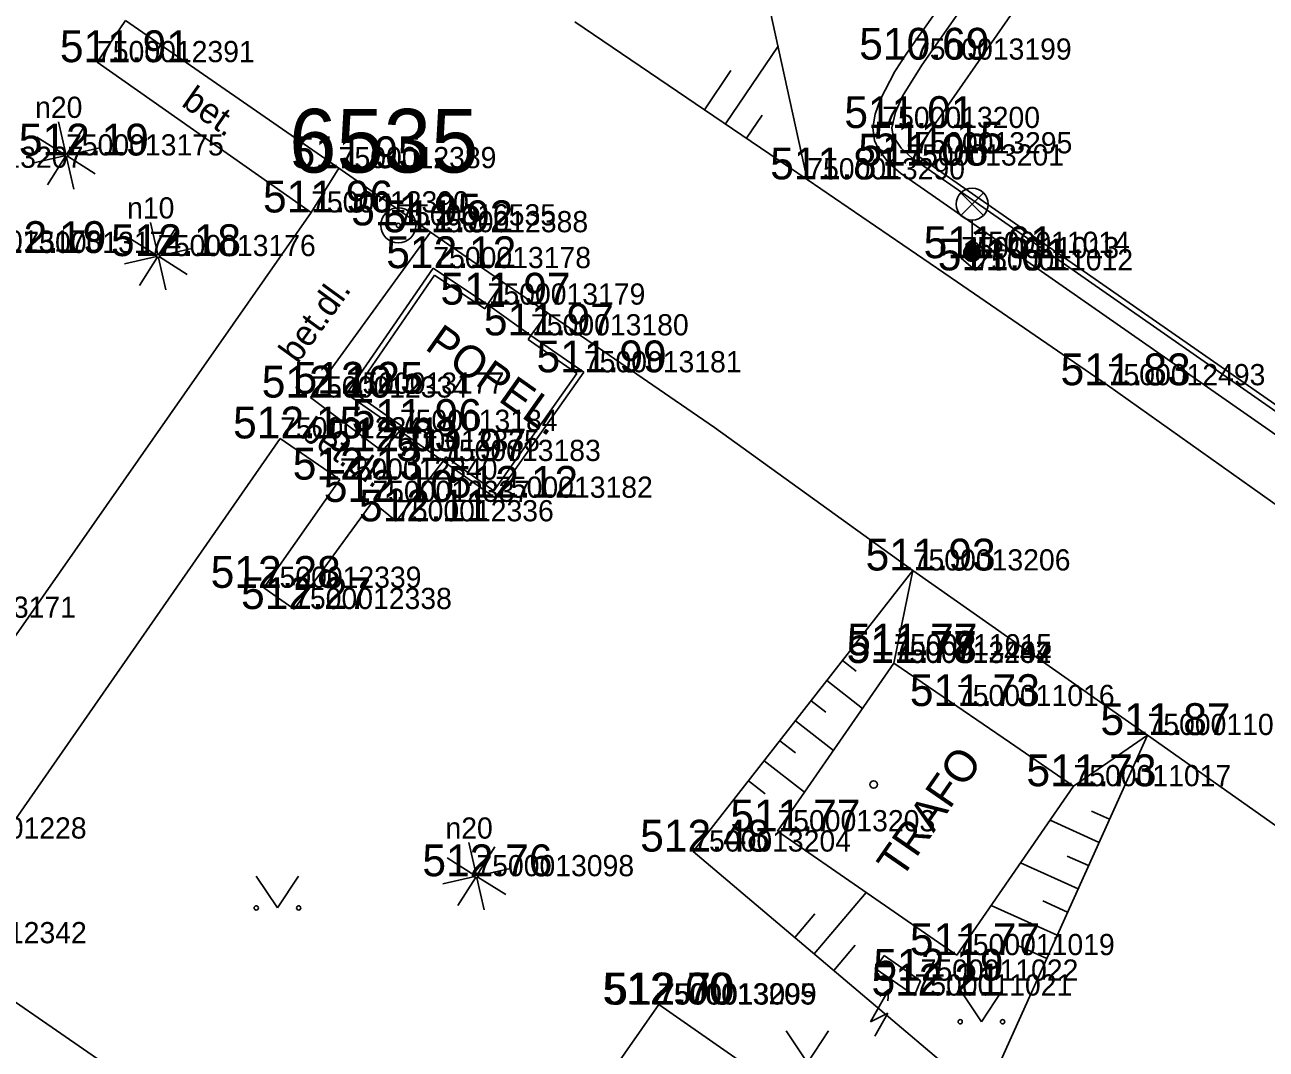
# Model space of a CAD drawing. Extents: x -669251 to -668549, y -1128351 to -1127698.
# Drawn here: x -668939.39 to -668910.12, y -1127892.22 to -1127868.08 of the extents above; entities that cross this region are included whole.
import ezdxf

# ---------------------------------------------------------------- set-up
doc = ezdxf.new("R2010")
doc.units = 0
for name, color, linetype in [('Vrstva 1', 7, 'Continuous'), ('Vrstva 10', 7, 'Continuous'), ('Vrstva 11', 7, 'Continuous'), ('Vrstva 14', 7, 'Continuous'), ('Vrstva 15', 7, 'Continuous'), ('Vrstva 2', 7, 'Continuous'), ('Vrstva 22', 7, 'Continuous'), ('Vrstva 24', 7, 'Continuous'), ('Vrstva 3', 7, 'Continuous'), ('Vrstva 33', 7, 'Continuous'), ('Vrstva 36', 7, 'Continuous'), ('Vrstva 40', 7, 'Continuous'), ('Vrstva 42', 7, 'Continuous'), ('Vrstva 47', 7, 'Continuous'), ('Vrstva 5', 7, 'Continuous'), ('Vrstva 58', 7, 'Continuous'), ('Vrstva 6', 7, 'Continuous'), ('Vrstva 63', 7, 'Continuous'), ('Vrstva 7', 7, 'Continuous')]:
    doc.layers.add(name, color=color, linetype=linetype)

msp = doc.modelspace()

# ---------------------------------------------------------------- linework, layer by layer
at = {"layer": 'Vrstva 1'}
for p, q in [((-668937.686, -1127868.956), (-668937.686, -1127868.956)), ((-668918.425, -1127868.897), (-668918.425, -1127868.897)), ((-668919.171, -1127870.508), (-668919.171, -1127870.508)), ((-668938.416, -1127871.156), (-668938.416, -1127871.156)), ((-668918.409, -1127871.106), (-668918.409, -1127871.106)), ((-668931.988, -1127871.455), (-668931.988, -1127871.455)), ((-668918.605, -1127871.394), (-668918.605, -1127871.394)), ((-668920.94, -1127871.719), (-668920.94, -1127871.719)), ((-668932.638, -1127872.499), (-668932.638, -1127872.499)), ((-668930.582, -1127872.804), (-668930.582, -1127872.804)), ((-668930.582, -1127872.804), (-668930.582, -1127872.804)), ((-668929.825, -1127872.966), (-668929.825, -1127872.966)), ((-668936.247, -1127873.528), (-668936.247, -1127873.528)), ((-668917.308, -1127873.577), (-668917.308, -1127873.577)), ((-668917.052, -1127873.453), (-668917.052, -1127873.453)), ((-668929.757, -1127873.812), (-668929.757, -1127873.812)), ((-668916.976, -1127873.865), (-668916.976, -1127873.865)), ((-668928.476, -1127874.672), (-668928.476, -1127874.672)), ((-668927.454, -1127875.397), (-668927.454, -1127875.397)), ((-668926.207, -1127876.268), (-668926.207, -1127876.268)), ((-668913.858, -1127876.573), (-668913.858, -1127876.573)), ((-668932.656, -1127876.863), (-668932.656, -1127876.863)), ((-668931.801, -1127876.772), (-668931.801, -1127876.772)), ((-668930.546, -1127877.65), (-668930.546, -1127877.65)), ((-668933.368, -1127877.826), (-668933.368, -1127877.826)), ((-668930.965, -1127878.128), (-668930.965, -1127878.128)), ((-668929.527, -1127878.359), (-668929.527, -1127878.359)), ((-668931.961, -1127878.798), (-668931.961, -1127878.798)), ((-668928.3, -1127879.226), (-668928.3, -1127879.226)), ((-668931.193, -1127879.323), (-668931.193, -1127879.323)), ((-668930.635, -1127879.781), (-668930.635, -1127879.781)), ((-668918.453, -1127880.94), (-668918.453, -1127880.94)), ((-668933.754, -1127881.349), (-668933.754, -1127881.349)), ((-668933.038, -1127881.849), (-668933.038, -1127881.849)), ((-668918.888, -1127882.941), (-668918.888, -1127882.941)), ((-668918.903, -1127883.115), (-668918.903, -1127883.115)), ((-668918.903, -1127883.116), (-668918.903, -1127883.116)), ((-668918.9, -1127883.121), (-668918.9, -1127883.121)), ((-668917.412, -1127884.136), (-668917.412, -1127884.136)), ((-668912.918, -1127884.819), (-668912.918, -1127884.819)), ((-668914.663, -1127886.026), (-668914.663, -1127886.026)), ((-668921.643, -1127887.089), (-668921.643, -1127887.089)), ((-668923.628, -1127887.567), (-668923.628, -1127887.567)), ((-668928.741, -1127888.148), (-668928.741, -1127888.148)), ((-668917.41, -1127890.008), (-668917.41, -1127890.008)), ((-668918.267, -1127890.61), (-668918.267, -1127890.61)), ((-668924.459, -1127891.17), (-668924.459, -1127891.17)), ((-668924.438, -1127891.175), (-668924.438, -1127891.175)), ((-668918.411, -1127890.962), (-668918.411, -1127890.962))]:
    msp.add_line(p, q, dxfattribs=at)
at = {"layer": 'Vrstva 10'}
for p, q in [((-668918.18, -1127868.156), (-668915.19, -1127863.895)), ((-668937.686, -1127868.956), (-668937.017, -1127867.976)), ((-668937.017, -1127867.976), (-668931.988, -1127871.455)), ((-668920.94, -1127871.719), (-668926.424, -1127868.005)), ((-668932.638, -1127872.499), (-668937.686, -1127868.956)), ((-668931.988, -1127871.455), (-668929.825, -1127872.966)), ((-668917.557, -1127871.85), (-668909.122, -1127877.73)), ((-668917.814, -1127872.219), (-668909.391, -1127878.091)), ((-668932.638, -1127872.499), (-668953.974, -1127903.041)), ((-668929.825, -1127872.966), (-668932.656, -1127876.863)), ((-668916.98, -1127873.199), (-668917.308, -1127873.577)), ((-668916.648, -1127873.487), (-668916.98, -1127873.199)), ((-668917.308, -1127873.577), (-668916.976, -1127873.865)), ((-668916.648, -1127873.487), (-668916.976, -1127873.865)), ((-668928.476, -1127874.672), (-668928.114, -1127874.142)), ((-668927.454, -1127875.397), (-668927.064, -1127874.864)), ((-668932.656, -1127876.863), (-668930.965, -1127878.128)), ((-668930.965, -1127878.128), (-668930.546, -1127877.65)), ((-668933.368, -1127877.826), (-668941.646, -1127889.728)), ((-668933.368, -1127877.826), (-668931.961, -1127878.798)), ((-668930.635, -1127879.781), (-668929.527, -1127878.359)), ((-668931.961, -1127878.798), (-668933.754, -1127881.349)), ((-668933.038, -1127881.849), (-668931.193, -1127879.323)), ((-668931.193, -1127879.323), (-668930.635, -1127879.781)), ((-668918.453, -1127880.94), (-668912.918, -1127884.819)), ((-668933.754, -1127881.349), (-668933.038, -1127881.849)), ((-668941.646, -1127889.728), (-668930.773, -1127897.183))]:
    msp.add_line(p, q, dxfattribs=at)
for points in [[(-668917.392, -1127867.816), (-668917.816, -1127868.421), (-668918.241, -1127869.026), (-668918.695, -1127869.754), (-668918.862, -1127870.135), (-668918.946, -1127870.508), (-668918.914, -1127870.701), (-668918.729, -1127870.985), (-668918.471, -1127871.214), (-668918.014, -1127871.532), (-668917.557, -1127871.85)], [(-668918.18, -1127868.156), (-668918.395, -1127868.462), (-668918.609, -1127868.768), (-668918.879, -1127869.179), (-668919.221, -1127869.844), (-668919.336, -1127870.18), (-668919.396, -1127870.508), (-668919.356, -1127870.799), (-668919.254, -1127871.02), (-668919.021, -1127871.329), (-668918.739, -1127871.574), (-668918.277, -1127871.897), (-668917.814, -1127872.219)], [(-668920.94, -1127871.719), (-668917.399, -1127874.146), (-668913.858, -1127876.573), (-668908.746, -1127880.198), (-668903.643, -1127883.845), (-668902.475, -1127884.553), (-668901.24, -1127885.179), (-668900.643, -1127885.444), (-668899.726, -1127885.752), (-668898.8, -1127885.974), (-668897.949, -1127886.123), (-668897.173, -1127886.216), (-668896.481, -1127886.261), (-668895.264, -1127886.241), (-668894.37, -1127886.127), (-668893.723, -1127885.975), (-668893.256, -1127885.821), (-668892.593, -1127885.518), (-668891.985, -1127885.123), (-668889.349, -1127883.09), (-668886.713, -1127881.057)], [(-668929.825, -1127872.966), (-668928.114, -1127874.142), (-668927.064, -1127874.864), (-668923.128, -1127877.569), (-668918.453, -1127880.94)], [(-668903.409, -1127892.816), (-668904.098, -1127891.771), (-668904.901, -1127890.785), (-668905.468, -1127890.18), (-668906.088, -1127889.65), (-668909.503, -1127887.234), (-668912.918, -1127884.819)]]:
    msp.add_lwpolyline(points, dxfattribs=at)
at = {"layer": 'Vrstva 11'}
for p, q in [((-668931.988, -1127871.455), (-668932.638, -1127872.499)), ((-668928.476, -1127874.672), (-668927.454, -1127875.397)), ((-668930.546, -1127877.65), (-668929.527, -1127878.359))]:
    msp.add_line(p, q, dxfattribs=at)
at = {"layer": 'Vrstva 14'}
for p, q in [((-668921.884, -1127867.416), (-668920.94, -1127871.719)), ((-668923.628, -1127887.567), (-668918.453, -1127880.94)), ((-668918.453, -1127880.94), (-668918.9, -1127883.121)), ((-668912.918, -1127884.819), (-668916.774, -1127893.365)), ((-668914.663, -1127886.026), (-668912.918, -1127884.819)), ((-668916.774, -1127893.365), (-668923.628, -1127887.567))]:
    msp.add_line(p, q, dxfattribs=at)
at = {"layer": 'Vrstva 15'}
for p, q in [((-668922.869, -1127870.413), (-668921.628, -1127868.581)), ((-668923.366, -1127870.076), (-668922.742, -1127869.155)), ((-668922.372, -1127870.749), (-668922.004, -1127870.205)), ((-668920.111, -1127883.063), (-668919.786, -1127883.317)), ((-668920.48, -1127883.535), (-668919.64, -1127884.191)), ((-668920.849, -1127884.009), (-668920.502, -1127884.28)), ((-668921.218, -1127884.481), (-668920.323, -1127885.18)), ((-668921.588, -1127884.954), (-668921.219, -1127885.242)), ((-668921.957, -1127885.427), (-668921.007, -1127886.169)), ((-668922.326, -1127885.9), (-668921.935, -1127886.205)), ((-668914.06, -1127887.351), (-668915.217, -1127886.829)), ((-668913.814, -1127886.804), (-668914.237, -1127886.613)), ((-668914.307, -1127887.898), (-668914.81, -1127887.671)), ((-668914.554, -1127888.445), (-668915.91, -1127887.833)), ((-668920.776, -1127889.98), (-668919.551, -1127888.532)), ((-668915.048, -1127889.539), (-668916.603, -1127888.838)), ((-668914.801, -1127888.992), (-668915.383, -1127888.729)), ((-668921.234, -1127889.593), (-668920.759, -1127889.031)), ((-668920.317, -1127890.367), (-668919.812, -1127889.77)), ((-668915.294, -1127890.086), (-668915.956, -1127889.787))]:
    msp.add_line(p, q, dxfattribs=at)
at = {"layer": 'Vrstva 22'}
for p, q in [((-668938.424, -1127871.116), (-668938.596, -1127870.362)), ((-668937.982, -1127870.466), (-668938.396, -1127871.122)), ((-668938.45, -1127871.136), (-668939.106, -1127870.722)), ((-668938.376, -1127871.148), (-668937.622, -1127870.976)), ((-668939.21, -1127871.336), (-668938.456, -1127871.164)), ((-668938.436, -1127871.19), (-668938.85, -1127871.846)), ((-668938.408, -1127871.196), (-668938.236, -1127871.95)), ((-668937.726, -1127871.59), (-668938.382, -1127871.176)), ((-668936.255, -1127873.488), (-668936.427, -1127872.734)), ((-668936.281, -1127873.508), (-668936.937, -1127873.094)), ((-668935.813, -1127872.838), (-668936.227, -1127873.494)), ((-668936.207, -1127873.52), (-668935.453, -1127873.348)), ((-668937.041, -1127873.708), (-668936.287, -1127873.536)), ((-668936.267, -1127873.562), (-668936.681, -1127874.218)), ((-668936.239, -1127873.568), (-668936.067, -1127874.322)), ((-668935.557, -1127873.962), (-668936.213, -1127873.548)), ((-668928.749, -1127888.108), (-668928.921, -1127887.354)), ((-668928.775, -1127888.128), (-668929.431, -1127887.714)), ((-668928.307, -1127887.458), (-668928.721, -1127888.114)), ((-668928.701, -1127888.14), (-668927.947, -1127887.968)), ((-668929.535, -1127888.328), (-668928.781, -1127888.156)), ((-668928.761, -1127888.182), (-668929.175, -1127888.838)), ((-668928.733, -1127888.188), (-668928.561, -1127888.942)), ((-668928.051, -1127888.582), (-668928.707, -1127888.168))]:
    msp.add_line(p, q, dxfattribs=at)
for centre in [(-668938.416, -1127871.156), (-668936.247, -1127873.528), (-668928.741, -1127888.148)]:
    msp.add_circle(centre, 0.04, dxfattribs=at)
at = {"layer": 'Vrstva 24'}
for p, q in [((-668919.342, -1127890.32), (-668919.131, -1127890.014)), ((-668919.131, -1127890.014), (-668918.267, -1127890.61)), ((-668919.342, -1127890.32), (-668918.411, -1127890.962)), ((-668918.267, -1127890.61), (-668918.411, -1127890.962)), ((-668919.446, -1127891.581), (-668919.017, -1127890.818)), ((-668919.017, -1127890.818), (-668919.232, -1127890.978)), ((-668919.041, -1127891.085), (-668919.017, -1127890.818)), ((-668919.044, -1127891.376), (-668919.446, -1127891.581)), ((-668919.351, -1127891.922), (-668919.044, -1127891.376))]:
    msp.add_line(p, q, dxfattribs=at)
at = {"layer": 'Vrstva 33'}
for p, q in [((-668917.317, -1127872.038), (-668916.787, -1127872.568)), ((-668917.317, -1127872.568), (-668916.787, -1127872.038)), ((-668917.052, -1127873.453), (-668917.052, -1127872.678))]:
    msp.add_line(p, q, dxfattribs=at)
for centre, radius in [((-668917.052, -1127872.303), 0.375), ((-668917.052, -1127873.453), 0.2), ((-668917.052, -1127873.453), 0.18), ((-668917.052, -1127873.453), 0.16), ((-668917.052, -1127873.453), 0.14), ((-668917.052, -1127873.453), 0.12), ((-668917.052, -1127873.453), 0.1), ((-668917.052, -1127873.453), 0.08), ((-668917.052, -1127873.453), 0.06), ((-668917.052, -1127873.453), 0.04), ((-668917.052, -1127873.453), 0.02)]:
    msp.add_circle(centre, radius, dxfattribs=at)
at = {"layer": 'Vrstva 36'}
for p, q in [((-668933.932, -1127888.145), (-668933.432, -1127888.895)), ((-668933.432, -1127888.895), (-668932.932, -1127888.145)), ((-668917.335, -1127890.828), (-668916.835, -1127891.578)), ((-668916.835, -1127891.578), (-668916.335, -1127890.828)), ((-668921.438, -1127891.794), (-668920.938, -1127892.544)), ((-668920.938, -1127892.544), (-668920.438, -1127891.794))]:
    msp.add_line(p, q, dxfattribs=at)
for centre in [(-668933.931, -1127888.894), (-668932.931, -1127888.894), (-668917.335, -1127891.578), (-668916.335, -1127891.578)]:
    msp.add_circle(centre, 0.05, dxfattribs=at)
at = {"layer": 'Vrstva 5'}
for p, q in [((-668918.409, -1127871.106), (-668914.147, -1127864.976)), ((-668909.047, -1127877.624), (-668918.409, -1127871.106)), ((-668921.643, -1127887.089), (-668918.9, -1127883.121)), ((-668918.9, -1127883.121), (-668917.412, -1127884.136)), ((-668916.176, -1127884.986), (-668914.663, -1127886.026)), ((-668914.663, -1127886.026), (-668917.41, -1127890.008)), ((-668917.41, -1127890.008), (-668921.643, -1127887.089)), ((-668924.438, -1127891.175), (-668928.706, -1127897.253)), ((-668915.075, -1127897.683), (-668924.438, -1127891.175))]:
    msp.add_line(p, q, dxfattribs=at)
at = {"layer": 'Vrstva 58'}
msp.add_circle((-668919.374, -1127885.986), 0.0875, dxfattribs=at)
at = {"layer": 'Vrstva 6'}
msp.add_line((-668916.176, -1127884.986), (-668917.412, -1127884.136), dxfattribs=at)
at = {"layer": 'Vrstva 63'}
for radius in [0.412, 0.412, 0.05, 0.05]:
    msp.add_circle((-668930.582, -1127872.804), radius, dxfattribs=at)
at = {"layer": 'Vrstva 7'}
for p, q in [((-668931.801, -1127876.772), (-668929.757, -1127873.812)), ((-668931.634, -1127876.742), (-668929.726, -1127873.978)), ((-668929.757, -1127873.812), (-668928.476, -1127874.672)), ((-668929.726, -1127873.978), (-668928.543, -1127874.772)), ((-668928.543, -1127874.772), (-668928.476, -1127874.672)), ((-668927.454, -1127875.397), (-668927.523, -1127875.495)), ((-668927.454, -1127875.397), (-668926.207, -1127876.268)), ((-668927.523, -1127875.495), (-668926.375, -1127876.297)), ((-668926.375, -1127876.297), (-668928.329, -1127879.059)), ((-668926.207, -1127876.268), (-668928.3, -1127879.226)), ((-668930.546, -1127877.65), (-668931.801, -1127876.772)), ((-668930.477, -1127877.552), (-668931.634, -1127876.742)), ((-668930.546, -1127877.65), (-668930.477, -1127877.552)), ((-668929.458, -1127878.261), (-668929.527, -1127878.359)), ((-668928.3, -1127879.226), (-668929.527, -1127878.359)), ((-668928.329, -1127879.059), (-668929.458, -1127878.261))]:
    msp.add_line(p, q, dxfattribs=at)

# ---------------------------------------------------------------- texts
at = {"layer": 'Vrstva 2'}
for s, p in [('7500013199', (-668918.425, -1127868.897)), ('7500012391', (-668937.686, -1127868.956)), ('7500013200', (-668919.171, -1127870.508)), ('7500013175', (-668938.416, -1127871.156)), ('7500013295', (-668918.409, -1127871.106)), ('7500013207', (-668941.728, -1127871.447)), ('7500012389', (-668931.988, -1127871.455)), ('7500013201', (-668918.605, -1127871.394)), ('7500013290', (-668920.94, -1127871.719)), ('7500012390', (-668932.638, -1127872.499)), ('7500016535', (-668930.582, -1127872.804)), ('7500016535', (-668930.582, -1127872.804)), ('7500012388', (-668929.825, -1127872.966)), ('7500013173', (-668941.296, -1127873.424)), ('7500013174', (-668939.42, -1127873.455)), ('7500013176', (-668936.247, -1127873.528)), ('7500011013', (-668917.308, -1127873.577)), ('7500011014', (-668917.052, -1127873.453)), ('7500013178', (-668929.757, -1127873.812)), ('7500011012', (-668916.976, -1127873.865)), ('7500013179', (-668928.476, -1127874.672)), ('7500013180', (-668927.454, -1127875.397)), ('7500013181', (-668926.207, -1127876.268)), ('7500013177', (-668931.801, -1127876.772)), ('7500012493', (-668913.858, -1127876.573)), ('7500012334', (-668932.656, -1127876.863)), ('7500013184', (-668930.546, -1127877.65)), ('7500012341', (-668933.368, -1127877.826)), ('7500012335', (-668930.965, -1127878.128)), ('7500013183', (-668929.527, -1127878.359)), ('7500012340', (-668931.961, -1127878.798)), ('7500012337', (-668931.193, -1127879.323)), ('7500013182', (-668928.3, -1127879.226)), ('7500012336', (-668930.635, -1127879.781)), ('7500013206', (-668918.453, -1127880.94)), ('7500012339', (-668933.754, -1127881.349)), ('7500013171', (-668941.901, -1127882.055)), ('7500012338', (-668933.038, -1127881.849)), ('7500011015', (-668918.888, -1127882.941)), ('7500012484', (-668918.903, -1127883.115)), ('7500012447', (-668918.903, -1127883.116)), ('7500013202', (-668918.9, -1127883.121)), ('7500011016', (-668917.412, -1127884.136)), ('7500011018', (-668912.918, -1127884.819)), ('7500011017', (-668914.663, -1127886.026)), ('3204001228', (-668941.65, -1127887.26)), ('7500013203', (-668921.643, -1127887.089)), ('7500013204', (-668923.628, -1127887.567)), ('7500013098', (-668928.741, -1127888.148)), ('7500012342', (-668941.646, -1127889.728)), ('7500011019', (-668917.41, -1127890.008)), ('7500011022', (-668918.267, -1127890.61)), ('7500011021', (-668918.411, -1127890.962)), ('7500013205', (-668924.459, -1127891.17)), ('7500013099', (-668924.438, -1127891.175))]:
    msp.add_text(s, height=0.5, dxfattribs=at).set_placement(p)
at = {"layer": 'Vrstva 3'}
for s, p in [('511.91 ', (-668938.562, -1127868.956)), ('510.69 ', (-668919.715, -1127868.897)), ('511.01 ', (-668920.066, -1127870.508)), ('512.19 ', (-668939.53, -1127871.156)), ('511.15 ', (-668919.377, -1127871.106)), ('511.95 ', (-668933.1, -1127871.455)), ('511.08 ', (-668919.737, -1127871.394)), ('511.81 ', (-668921.814, -1127871.719)), ('511.96 ', (-668933.773, -1127872.499)), ('511.95 ', (-668931.694, -1127872.804)), ('511.95 ', (-668931.694, -1127872.804)), ('511.92 ', (-668930.937, -1127872.966)), ('512.19 ', (-668940.534, -1127873.455)), ('512.18 ', (-668937.357, -1127873.528)), ('512.12 ', (-668930.867, -1127873.812)), ('511.61 ', (-668918.196, -1127873.577)), ('511.61 ', (-668917.864, -1127873.865)), ('511.97 ', (-668929.588, -1127874.672)), ('511.97 ', (-668928.566, -1127875.397)), ('511.99 ', (-668927.323, -1127876.268)), ('512.25 ', (-668933.053, -1127876.772)), ('511.83 ', (-668914.968, -1127876.573)), ('512.10 ', (-668933.802, -1127876.863)), ('511.96 ', (-668931.681, -1127877.65)), ('512.15 ', (-668934.478, -1127877.826)), ('512.03 ', (-668932.239, -1127878.128)), ('511.97 ', (-668930.639, -1127878.359)), ('512.13 ', (-668933.071, -1127878.798)), ('512.10 ', (-668932.339, -1127879.323)), ('512.12 ', (-668929.41, -1127879.226)), ('512.11 ', (-668931.509, -1127879.781)), ('511.93 ', (-668919.565, -1127880.94)), ('512.28 ', (-668935.006, -1127881.349)), ('512.27 ', (-668934.29, -1127881.849)), ('511.78 ', (-668920.013, -1127883.115)), ('511.77 ', (-668920.013, -1127883.116)), ('511.78 ', (-668920.01, -1127883.121)), ('511.77 ', (-668919.998, -1127882.941)), ('511.73 ', (-668918.522, -1127884.136)), ('511.87 ', (-668914.028, -1127884.819)), ('511.73 ', (-668915.773, -1127886.026)), ('511.77 ', (-668922.753, -1127887.089)), ('512.48 ', (-668924.88, -1127887.567)), ('512.76 ', (-668930.015, -1127888.148)), ('511.77 ', (-668918.52, -1127890.008)), ('512.19 ', (-668919.381, -1127890.61)), ('512.21 ', (-668919.426, -1127890.962)), ('512.00 ', (-668925.768, -1127891.17)), ('512.70 ', (-668925.726, -1127891.175))]:
    msp.add_text(s, height=0.75, dxfattribs=at).set_placement(p)
at = {"layer": 'Vrstva 40'}
for s, rotation, p in [('bet.', 324.9364, (-668935.722, -1127869.97)), ('bet.dl.', 54.0032, (-668932.956, -1127876.085)), ('bet.dl.', 325.3621, (-668932.926, -1127877.776))]:
    msp.add_text(s, height=0.6, rotation=rotation, dxfattribs=at).set_placement(p)
at = {"layer": 'Vrstva 42'}
for s, rotation, p in [('POPEL.', 324.8148, (-668929.982, -1127875.709)), ('TRAFO', 55.4, (-668918.724, -1127888.238))]:
    msp.add_text(s, height=0.75, rotation=rotation, dxfattribs=at).set_placement(p)
at = {"layer": 'Vrstva 47'}
for s, p in [('n20', (-668939.146, -1127870.27)), ('n10', (-668936.977, -1127872.642)), ('n20', (-668929.471, -1127887.262))]:
    msp.add_text(s, height=0.5, dxfattribs=at).set_placement(p)
at = {"layer": 'Vrstva 63'}
msp.add_text('6535', height=1.5, dxfattribs=at).set_placement((-668933.156, -1127871.558))
msp.add_text('6535', height=1.5, dxfattribs=at).set_placement((-668933.156, -1127871.558))

doc.saveas('drawing.dxf')
